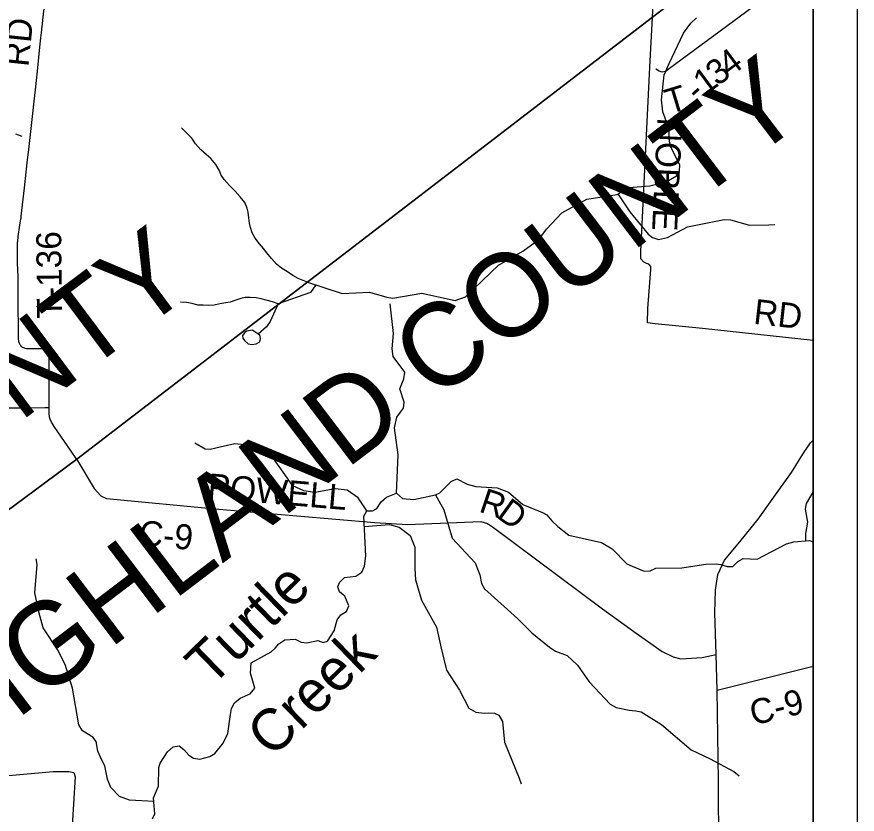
# Model space of a CAD drawing. Extents: x 0 to 48.6, y 0 to 22.
# Drawn here: x 7.09 to 9, y 17.478 to 19.291 of the extents above; entities that cross this region are included whole.
import ezdxf

# ---------------------------------------------------------------- set-up
doc = ezdxf.new("R2010")
doc.units = 0
for name, color, linetype in [('GM_X_Corporation', 7, 'Continuous'), ('GM_X_County_Road', 7, 'Continuous'), ('GM_X_County_Road_Text', 7, 'Continuous'), ('GM_X_County_Text', 7, 'Continuous'), ('GM_X_Minor_Lake', 7, 'Continuous'), ('GM_X_Minor_River', 7, 'Continuous'), ('GM_X_Minor_River_Text', 7, 'Continuous'), ('GM_X_Township_Road', 7, 'Continuous'), ('GM_X_Township_Road_Text', 7, 'Continuous'), ('SH_Data', 7, 'Continuous')]:
    doc.layers.add(name, color=color, linetype=linetype)

msp = doc.modelspace()

# ---------------------------------------------------------------- linework, layer by layer
at = {"layer": 'GM_X_Corporation'}
msp.add_lwpolyline([(6.9471, 18.0777), (7.2261, 18.2847), (8.5348, 19.2897), (8.9, 19.5692), (8.9, 20.9), (2.1, 20.9)], dxfattribs=at)
for points in [[(8.9, 19.5692), (8.9, 20.9), (5.795, 20.9), (5.8236, 20.7829), (6.0412, 19.8859), (6.2759, 18.9159), (6.3396, 18.6531), (6.4996, 17.9212), (6.5365, 17.7727), (6.9471, 18.0777), (7.2261, 18.2847), (8.5348, 19.2897)], [(5.0944, 14.1), (8.9, 14.1), (8.9, 19.5692), (8.5348, 19.2897), (7.2261, 18.2847), (6.9471, 18.0777), (6.5365, 17.7727), (5.8387, 17.2541), (5.5264, 17.0064), (4.6225, 16.3345), (4.044, 15.9033), (4.0346, 15.8959), (4.0398, 15.887), (4.3544, 15.3539), (4.4679, 15.1616), (4.7542, 14.6766)]]:
    msp.add_lwpolyline(points, close=True, dxfattribs=at)
at = {"layer": 'GM_X_County_Road'}
for q in [(8.6792, 17.8406), (8.9, 17.8146)]:
    msp.add_line((8.6814, 17.7601), q, dxfattribs=at)
for points in [[(8.6792, 17.8406), (8.6766, 17.9359), (8.6783, 17.9871), (8.6835, 18.023), (8.6987, 18.0553), (8.7332, 18.0973), (8.7748, 18.1485), (8.8071, 18.1929), (8.8505, 18.2547), (8.8762, 18.2962), (8.8936, 18.3219), (8.9, 18.328)], [(7.2264, 18.2841), (7.2659, 18.2181), (7.2806, 18.2018), (7.2934, 18.1954), (7.5492, 18.1711), (7.9035, 18.1409), (7.9778, 18.1366), (8.1449, 18.1432), (8.1596, 18.139), (8.1737, 18.1295), (8.4208, 17.9446), (8.4974, 17.8894), (8.5567, 17.848), (8.5821, 17.8356), (8.5995, 17.8313), (8.6474, 17.8338), (8.6792, 17.8406)], [(8.7903, 16.6409), (8.756, 16.7936), (8.7217, 16.9604), (8.7133, 17.013), (8.7028, 17.0786), (8.6997, 17.1041), (8.6913, 17.2315), (8.6903, 17.2915), (8.6855, 17.3963), (8.6851, 17.5535), (8.6814, 17.7601)], [(7.0193, 17.5612), (7.1388, 17.5717), (7.1722, 17.5746), (7.1927, 17.5752), (7.2079, 17.5751), (7.2192, 17.5729), (7.2224, 17.563), (7.2032, 17.2545), (7.0677, 16.7791)]]:
    msp.add_lwpolyline(points, dxfattribs=at)
at = {"layer": 'GM_X_Minor_Lake'}
for points in [[(7.6377, 18.5701), (7.6306, 18.5744), (7.6246, 18.5779), (7.6124, 18.5758), (7.6078, 18.5732), (7.6031, 18.5661), (7.6034, 18.56), (7.6075, 18.555), (7.6154, 18.5473), (7.6244, 18.5453), (7.6339, 18.5474), (7.642, 18.5518), (7.6436, 18.5586)], [(7.6436, 18.5586), (7.6432, 18.564), (7.6423, 18.5661), (7.6377, 18.5701)]]:
    msp.add_lwpolyline(points, dxfattribs=at)
at = {"layer": 'GM_X_Minor_River'}
for points in [[(7.7484, 18.6878), (7.8295, 18.6616), (7.8913, 18.6644), (7.9306, 18.6535), (7.9442, 18.6507), (8.0104, 18.6622), (8.0859, 18.6454), (8.1096, 18.6542), (8.185, 18.7262), (8.2397, 18.7576), (8.2762, 18.7847), (8.2936, 18.8079), (8.3287, 18.8449), (8.3853, 18.8759), (8.4545, 18.887), (8.4679, 18.8959), (8.4812, 18.9025), (8.5287, 18.9063), (8.5656, 18.9152), (8.5893, 18.9289), (8.5964, 18.9413), (8.5966, 18.9538), (8.58, 18.9863), (8.5741, 18.9997), (8.5721, 19.0376), (8.5579, 19.0743), (8.5553, 19.102), (8.5615, 19.1584), (8.5725, 19.1848), (8.605, 19.2537), (8.6217, 19.2765), (8.6344, 19.2881)], [(7.7484, 18.6878), (7.7295, 18.6955), (7.7171, 18.7028), (7.705, 18.7109), (7.6914, 18.7194), (7.6801, 18.7286), (7.6689, 18.7408), (7.658, 18.7542), (7.6508, 18.7638), (7.6418, 18.7741), (7.6313, 18.7871), (7.625, 18.7993), (7.6209, 18.8119), (7.6184, 18.8214), (7.6169, 18.8339), (7.6155, 18.8461), (7.6137, 18.8556), (7.6078, 18.8685), (7.5976, 18.8815), (7.5864, 18.8945), (7.5736, 18.9068), (7.5612, 18.9206), (7.5544, 18.9309), (7.55, 18.9423), (7.5421, 18.9545), (7.5309, 18.9683), (7.5199, 18.9775), (7.5079, 18.9882), (7.4959, 19.0016), (7.488, 19.015), (7.4756, 19.0265), (7.464, 19.0384)], [(7.0871, 19.0243), (7.101, 19.0192)], [(8.4559, 18.8879), (8.4834, 18.8471), (8.5251, 18.7964), (8.5348, 18.7886), (8.5484, 18.7843), (8.5689, 18.7889), (8.6141, 18.8128), (8.6974, 18.8297), (8.7118, 18.8291), (8.7552, 18.8167), (8.7992, 18.8175), (8.8125, 18.8185)], [(7.7697, 18.6809), (7.7575, 18.6638), (7.6837, 18.6378)], [(7.6837, 18.6378), (7.6714, 18.6425), (7.6566, 18.6464), (7.6453, 18.6496), (7.6339, 18.6519), (7.6203, 18.6528), (7.6089, 18.6522), (7.599, 18.6504), (7.5857, 18.6459), (7.5746, 18.6422), (7.5648, 18.6404), (7.5511, 18.6379), (7.5385, 18.635), (7.526, 18.6339), (7.5131, 18.6348), (7.5014, 18.6353), (7.4885, 18.6385), (7.4752, 18.6409), (7.462, 18.6421)], [(7.6837, 18.6378), (7.6658, 18.5977), (7.6577, 18.5861), (7.6388, 18.5691)], [(7.9528, 18.2075), (7.9564, 18.2947), (7.9487, 18.3559), (7.954, 18.3805), (7.9621, 18.3914), (7.9687, 18.4011), (7.9701, 18.4147), (7.9603, 18.4445), (7.9694, 18.4675), (7.9719, 18.4826), (7.9455, 18.5183), (7.9428, 18.5354), (7.946, 18.5706), (7.9383, 18.6383)], [(7.8851, 18.1673), (7.8654, 18.1971), (7.8411, 18.2142), (7.8138, 18.2173), (7.7674, 18.2089), (7.7425, 18.2131), (7.7169, 18.2245), (7.6735, 18.2866), (7.6487, 18.3056), (7.6212, 18.3159), (7.5856, 18.3195), (7.5518, 18.3124), (7.5297, 18.3067), (7.5183, 18.308), (7.4943, 18.3216)], [(7.8738, 18.0279), (7.8804, 18.0418), (7.8831, 18.0649), (7.8784, 18.1552), (7.8851, 18.1673), (7.898, 18.1674), (7.9083, 18.1726), (7.918, 18.1876), (7.9303, 18.1984), (7.9528, 18.2075), (7.9663, 18.1952), (7.992, 18.1933), (8.0418, 18.2035), (8.0514, 18.2087), (8.0768, 18.2341), (8.0902, 18.2403), (8.1135, 18.2282), (8.1331, 18.2229), (8.1816, 18.2195), (8.2073, 18.21), (8.2402, 18.1815), (8.2846, 18.1637), (8.2944, 18.1582), (8.306, 18.1448), (8.3198, 18.1317), (8.3449, 18.1119), (8.4189, 18.0956), (8.4433, 18.0812), (8.4766, 18.0473), (8.4882, 18.0414), (8.5157, 18.03), (8.5294, 18.0309), (8.5427, 18.0368), (8.6015, 18.0378), (8.6559, 18.0464), (8.6794, 18.0472), (8.69, 18.0455), (8.7047, 18.0407), (8.7176, 18.0409), (8.7288, 18.0525), (8.7406, 18.0588), (8.7728, 18.0579), (8.8397, 18.0925), (8.8557, 18.0972), (8.8918, 18.1), (8.9, 18.0972)], [(8.883, 18.0993), (8.883, 18.1161), (8.8879, 18.1414), (8.8827, 18.1711), (8.8848, 18.1843), (8.9, 18.2098)], [(8.0418, 18.2035), (8.0603, 18.1695), (8.0794, 18.1054), (8.1319, 18.0493), (8.1421, 18.0222), (8.1464, 18.0024), (8.153, 17.9898), (8.2282, 17.923), (8.2606, 17.8899), (8.3003, 17.8574), (8.3142, 17.8484), (8.3409, 17.8385), (8.3645, 17.8166), (8.3908, 17.7786), (8.4389, 17.7282), (8.4521, 17.72), (8.4816, 17.7142), (8.4971, 17.7128), (8.5092, 17.7108), (8.5554, 17.682), (8.6227, 17.624), (8.6656, 17.604), (8.7197, 17.5751), (8.7317, 17.5647)], [(7.8796, 18.1316), (7.9373, 18.1365), (7.9592, 18.1305), (7.9839, 18.1111), (7.9949, 18.0848), (7.9949, 18.0366), (7.9963, 18.0108), (8.01, 17.9643), (8.0436, 17.9031), (8.0542, 17.8551), (8.0663, 17.8049), (8.0963, 17.7597), (8.1176, 17.7191), (8.133, 17.7094), (8.1531, 17.7076), (8.1626, 17.7082), (8.1755, 17.7076), (8.1856, 17.7029), (8.1938, 17.6887), (8.1983, 17.6416), (8.2315, 17.5596), (8.2363, 17.547)], [(7.4011, 17.5064), (7.3458, 17.5093), (7.3235, 17.518), (7.3038, 17.5384), (7.2961, 17.5575), (7.2897, 17.5879), (7.2831, 17.6005), (7.274, 17.6208), (7.2701, 17.6432), (7.2627, 17.6528), (7.2391, 17.6676), (7.2309, 17.6806), (7.2167, 17.7643), (7.2001, 17.8184), (7.1821, 17.852), (7.1495, 17.9011), (7.1405, 17.935), (7.1377, 17.9483), (7.131, 17.9814), (7.1358, 18.0451), (7.1337, 18.0584)], [(7.3986, 17.4675), (7.4033, 17.4784), (7.4005, 17.5152), (7.4122, 17.5416), (7.4129, 17.5841), (7.4157, 17.5939), (7.4321, 17.6194), (7.4451, 17.631), (7.4588, 17.633), (7.4697, 17.6245), (7.4805, 17.6122), (7.4917, 17.6052), (7.5061, 17.6031), (7.5286, 17.6088), (7.5401, 17.6159), (7.559, 17.6395), (7.5692, 17.6609), (7.5756, 17.7044), (7.5777, 17.7177), (7.5847, 17.7308), (7.5978, 17.7413), (7.6203, 17.7515), (7.6311, 17.7642), (7.6214, 17.7985), (7.6229, 17.822), (7.6677, 17.8467), (7.6773, 17.8549), (7.6858, 17.8654), (7.6992, 17.8743), (7.7227, 17.8758), (7.7359, 17.8688), (7.7492, 17.8675), (7.7739, 17.8728), (7.7863, 17.8684), (7.7958, 17.8709), (7.811, 17.895), (7.8182, 17.9199), (7.826, 17.9311), (7.8394, 17.9385), (7.8449, 17.9513), (7.8357, 17.9731), (7.8234, 17.9831), (7.8198, 17.9946), (7.8234, 18.0044), (7.8349, 18.0156), (7.8604, 18.019), (7.8738, 18.0279)]]:
    msp.add_lwpolyline(points, dxfattribs=at)
at = {"layer": 'GM_X_Township_Road'}
for points in [[(8.535, 19.2892), (8.5379, 19.3551), (8.5421, 19.4351), (8.549, 19.5829), (8.5543, 19.7149)], [(8.5423, 19.1723), (8.5498, 19.1679), (8.555, 19.1655), (8.5649, 19.1671), (8.5704, 19.1715), (8.8068, 19.3467), (8.9, 19.4153)], [(7.1632, 18.4013), (7.1632, 18.4022), (7.1634, 18.4146), (7.1634, 18.4221), (7.1636, 18.4742), (7.1635, 18.4848), (7.1631, 18.5053), (7.1633, 18.5159), (7.1631, 18.5196), (7.1624, 18.5233), (7.1616, 18.5256), (7.1605, 18.5278), (7.159, 18.5298), (7.1578, 18.5312), (7.1553, 18.5329), (7.1536, 18.5338), (7.1501, 18.535), (7.1471, 18.5354), (7.1421, 18.5358), (7.1383, 18.5358), (7.1277, 18.5358), (7.1171, 18.5358), (7.1121, 18.5361), (7.1091, 18.5366), (7.1056, 18.5377), (7.1029, 18.539), (7.1005, 18.541), (7.0988, 18.543), (7.0974, 18.545), (7.0959, 18.5478), (7.0948, 18.5513), (7.0943, 18.5543), (7.094, 18.5587), (7.094, 18.5668), (7.094, 18.578), (7.0932, 18.637), (7.0928, 18.6724), (7.0927, 18.6979), (7.0921, 18.7165), (7.0917, 18.7301), (7.0913, 18.7556), (7.0914, 18.7669), (7.0914, 18.7699), (7.0916, 18.7749), (7.0918, 18.7779), (7.0919, 18.7804), (7.0923, 18.7838), (7.0927, 18.7874), (7.0932, 18.7909), (7.0969, 18.8167), (7.0992, 18.8311), (7.0997, 18.8339), (7.1, 18.837), (7.1071, 18.9018), (7.1135, 18.9585), (7.1177, 18.9955), (7.1232, 19.0436), (7.1264, 19.0708), (7.1295, 19.0986), (7.1324, 19.1245), (7.1371, 19.1671), (7.1425, 19.2215), (7.1448, 19.2431), (7.1467, 19.2609), (7.1471, 19.264), (7.1475, 19.2678), (7.15, 19.2899), (7.1561, 19.3436)], [(8.9, 18.5546), (8.6485, 18.5823), (8.5411, 18.5927), (8.5237, 18.5951), (8.5245, 18.6273), (8.5307, 18.716), (8.5312, 18.7228), (8.5261, 18.7286), (8.5193, 18.7303), (8.5141, 18.7339), (8.5085, 18.7401), (8.5086, 18.7568), (8.5284, 19.1761), (8.535, 19.2892)], [(7.1632, 18.4013), (7.1535, 18.4013), (7.1101, 18.4011), (7.071, 18.4006), (7.0499, 18.4004), (6.9996, 18.3996), (6.9673, 18.399), (6.9387, 18.3989), (6.9186, 18.3989)], [(7.2264, 18.2841), (7.2122, 18.3052), (7.1918, 18.3349), (7.175, 18.3595), (7.1702, 18.3668), (7.169, 18.3691), (7.1678, 18.3712), (7.1668, 18.3733), (7.1659, 18.3758), (7.1652, 18.378), (7.1645, 18.3805), (7.1641, 18.3832), (7.1637, 18.386), (7.1635, 18.3889), (7.1632, 18.3922), (7.1632, 18.4013)]]:
    msp.add_lwpolyline(points, dxfattribs=at)
at = {"layer": 'SH_Data'}
for p, q in [((9, 21), (9, 14)), ((8.9, 20.9), (8.9, 14.1))]:
    msp.add_line(p, q, dxfattribs=at)

# ---------------------------------------------------------------- texts
at = {"layer": 'GM_X_County_Road_Text'}
for s, height, rotation, p in [('POWELL', 0.05682, 355.1129, (7.5222, 18.1962)), ('R', 0.0568, 341.4182, (8.1379, 18.1663)), ('D', 0.0568, 324.2464, (8.1781, 18.1535)), ('C-9', 0.05682, 354.4738, (7.3657, 18.0899)), ('C-9', 0.05682, 13.9242, (8.7639, 17.6791))]:
    msp.add_text(s, height=height, rotation=rotation, dxfattribs=at).set_placement(p)
at = {"layer": 'GM_X_County_Text'}
for s, rotation, p in [('HIGHLAND COUNTY', 37.2438, (6.9412, 17.5789)), ('CLINTON COUNTY', 36.7754, (5.6985, 17.3231))]:
    msp.add_text(s, height=0.189394, rotation=rotation, dxfattribs=at).set_placement(p)
at = {"layer": 'GM_X_Minor_River_Text'}
for s, rotation, p in [('Turtle', 44.1863, (7.531, 17.7648)), ('Creek', 43.9898, (7.6701, 17.6037))]:
    msp.add_text(s, height=0.0947, rotation=rotation, dxfattribs=at).set_placement(p)
at = {"layer": 'GM_X_Township_Road_Text'}
for s, height, rotation, p in [('RD', 0.05682, 84.0908, (7.116, 19.1757)), ('4', 0.0568, 36.4015, (8.7105, 19.1525)), ('3', 0.0568, 36.4276, (8.6824, 19.1317)), ('1', 0.0568, 36.5389, (8.6543, 19.1109)), ('T', 0.0568, 16.8979, (8.5733, 19.0689)), ('-', 0.0568, 43.9869, (8.639, 19.0959)), ('NOBLE', 0.05682, 267.3225, (8.5459, 19.0622)), ('T-136', 0.05682, 90.5595, (7.1926, 18.605)), ('RD', 0.05682, 353.5502, (8.7627, 18.5929))]:
    msp.add_text(s, height=height, rotation=rotation, dxfattribs=at).set_placement(p)

doc.saveas('drawing.dxf')
